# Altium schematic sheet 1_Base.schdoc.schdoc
size 309 x 223 mm; Symbol: Sheet-Symbol_A4; Device: Sheet-Symbol_A4; Company: Velizy Astro Club; Drawed: Paul V.; Reviewed: Denis G.; Version: V1.0; Page Size: A4; @Project Name: NAFA AstrAlim; @Page Count: 2; @Update Date: 2024-01-05; @Create Date: 2023-12-12; @Schematic Name: AstrAlim NAFA; Part Number: AstrAlim-v1.0; @Page No: 1; @Page Name: Base
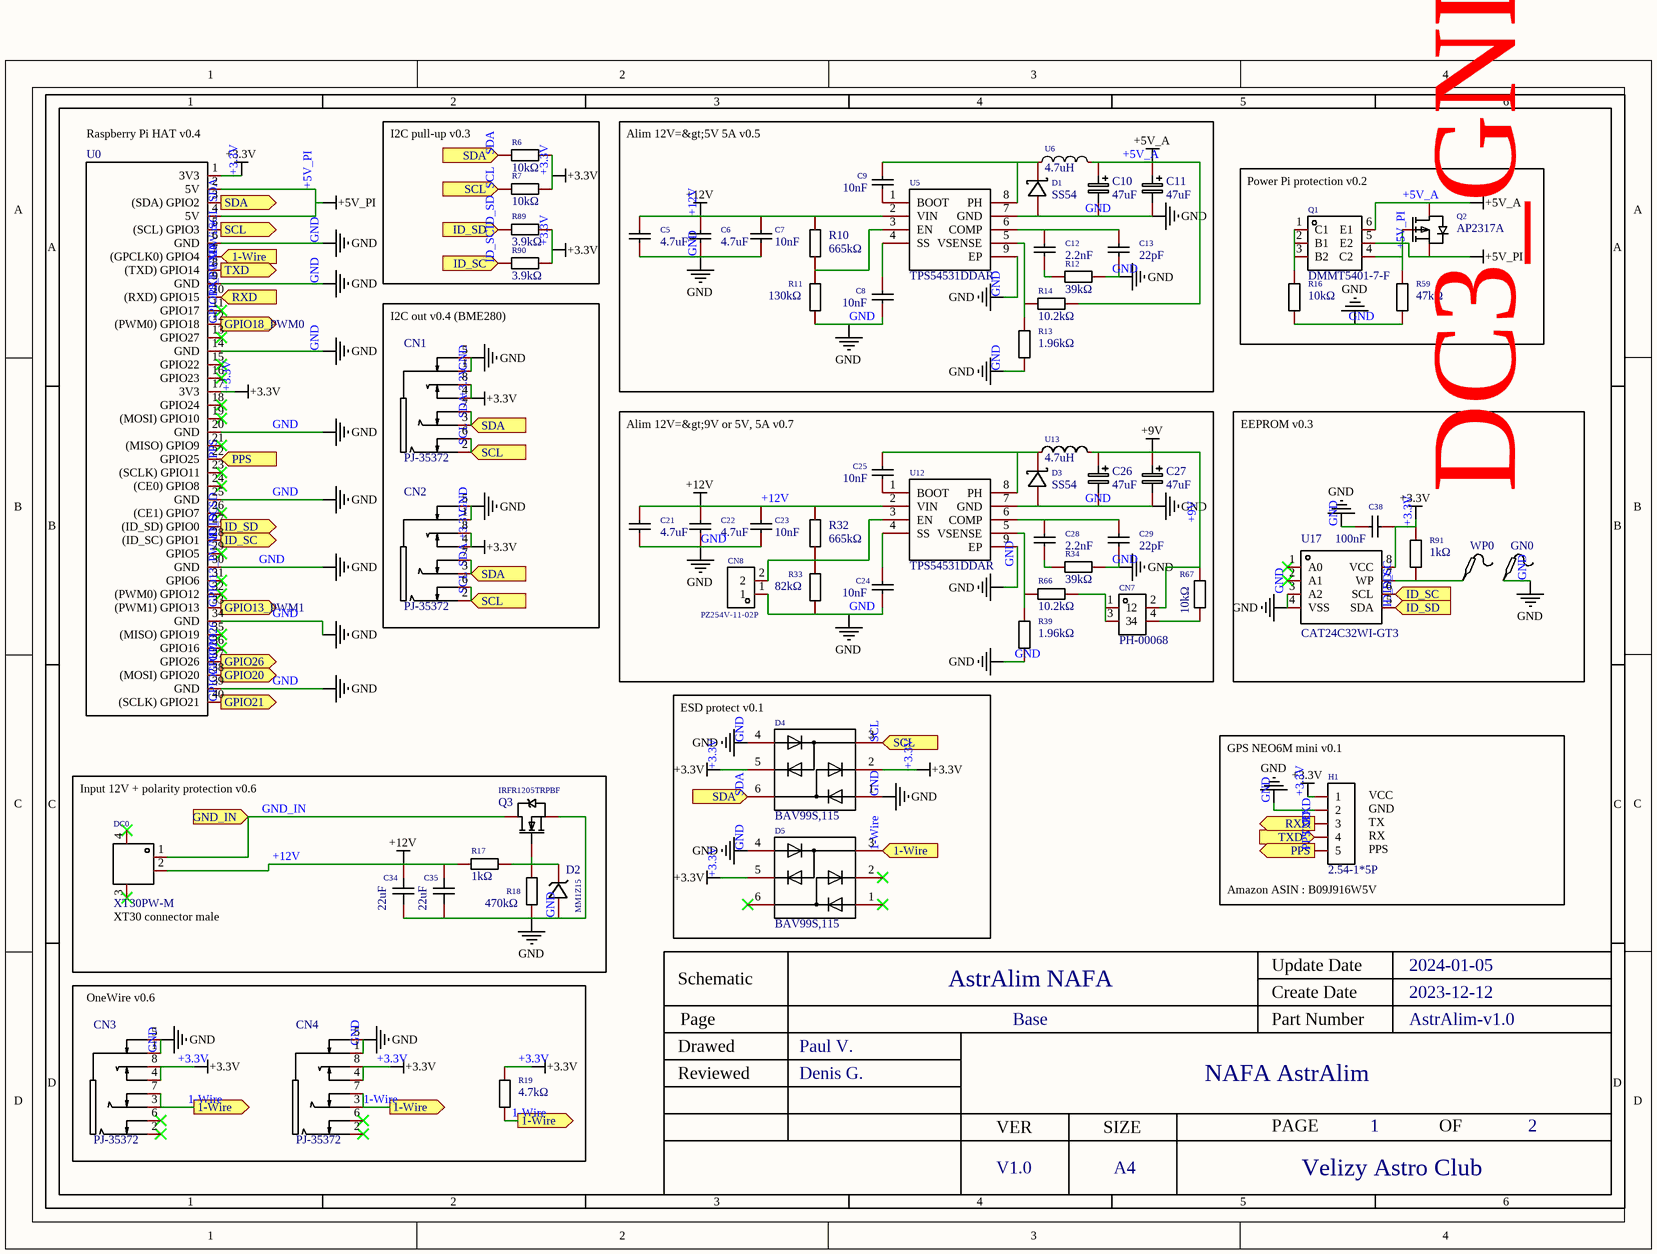
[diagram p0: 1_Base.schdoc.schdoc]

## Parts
C5  4.7uF  [C0805]
C6  4.7uF  [C0805]
C7  10nF  [C0402]
C8  10nF  [C0402]
C9  10nF  [C0402]
C10  47uF  [CAP-SMD_L3.5-W2.8-R-RD]
C11  47uF  [CAP-SMD_L3.5-W2.8-R-RD]
C12  2.2nF  [C0603]
C13  22pF  [C0402]
C21  4.7uF  [C0805]
C22  4.7uF  [C0805]
C23  10nF  [C0402]
C24  10nF  [C0402]
C25  10nF  [C0402]
C26  47uF  [CAP-SMD_L3.5-W2.8-R-RD]
C27  47uF  [CAP-SMD_L3.5-W2.8-R-RD]
C28  2.2nF  [C0603]
C29  22pF  [C0402]
C34  22uF  [C0805]
C35  22uF  [C0805]
C38  100nF  [C0402]
CN1  PJ-35372  [AUDIO-TH_PJ-35372]
CN2  PJ-35372  [AUDIO-TH_PJ-35372]
CN3  PJ-35372  [AUDIO-TH_PJ-35372]
CN4  PJ-35372  [AUDIO-TH_PJ-35372]
CN7  PH-00068  [HDR-TH_4P-P2.54-V-M-R2-C2-S2.54]
CN8  PZ254V-11-02P  [HDR-TH_2P-P2.54-V-M]
D1  SS54  [SMA_L4.4-W2.8-LS5.4-R-RD]
D2  MM1Z15  [SOD-123_L2.7-W1.6-LS3.7-RD]
D3  SS54  [SMA_L4.4-W2.8-LS5.4-R-RD]
D4  BAV99S,115  [SOT-363_L2.0-W1.3-P0.65-LS2.1-TL]
D5  BAV99S,115  [SOT-363_L2.0-W1.3-P0.65-LS2.1-TL]
DC0  XT30PW-M  [CONN-TH_XT30PW-F-1]
GN0  Test-Point  [Test-Point-0.5mm]  (value not drawn)
H1  2.54-1*5P  [HDR-TH_5P-P2.54-V-F]
Q1  DMMT5401-7-F  [SOT-23-6_L2.9-W1.6-P0.95-LS2.8-BR]
Q2  AP2317A  [SOT-23-3_L2.9-W1.6-P1.90-LS2.8-BR]
Q3  IRFR1205TRPBF  [TO-252-3_L6.5-W5.8-P4.58-BL]
R6  10kΩ  [R0402]
R7  10kΩ  [R0402]
R10  665kΩ  [R0603]
R11  130kΩ  [R0603]
R12  39kΩ  [R0603]
R13  1.96kΩ  [R0402]
R14  10.2kΩ  [R0402]
R16  10kΩ  [R0402]
R17  1kΩ  [R0402]
R18  470kΩ  [R0603]
R19  4.7kΩ  [R0402]
R32  665kΩ  [R0603]
R33  82kΩ  [R0603]
R34  39kΩ  [R0603]
R39  1.96kΩ  [R0402]
R59  47kΩ  [R0402]
R66  10.2kΩ  [R0402]
R67  10kΩ  [R0402]
R89  3.9kΩ  [R0603]
R90  3.9kΩ  [R0603]
R91  1kΩ  [R0402]
U0  RASPI HAT FULL  [RASBERRYPI-3-HAT-EXT]  (value not drawn)
U5  TPS54531DDAR  [SOIC-8_L5.0-W4.0-P1.27-LS6.0-BL-EP2.0]
U6  4.7uH  [IND-SMD_L7.2-W6.6_GPSR07X0]
U12  TPS54531DDAR  [SOIC-8_L5.0-W4.0-P1.27-LS6.0-BL-EP2.0]
U13  4.7uH  [IND-SMD_L7.2-W6.6_GPSR07X0]
U17  CAT24C32WI-GT3  [SOIC-8_L5.0-W4.0-P1.27-LS6.0-BL]
WP0  Test-Point  [Test-Point-0.5mm]  (value not drawn)

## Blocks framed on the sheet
I2C pull-up v0.3: R6 R7 R89 R90
Alim 12V=&gt;5V 5A v0.5: C5-C13 D1 R10-R14 U5 U6
Power Pi protection v0.2: Q1 Q2 R16 R59
I2C out v0.4 (BME280): CN1 CN2
Alim 12V=&gt;9V or 5V, 5A v0.7: C21-C29 CN7 CN8 D3 R32-R34 R39 R66 R67 U12 U13
EEPROM v0.3: C38 GN0 R91 U17 WP0
ESD protect v0.1: D4 D5
OneWire v0.6: CN3 CN4 R19

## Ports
1-Wire (in), 1-Wire (out), GND_IN (in), GPIO13_PWM1 (out), GPIO18_PWM0 (out), GPIO20 (out), GPIO21 (out), GPIO26 (out), ID_SC (in), ID_SC (out), ID_SD (in), ID_SD (out), PPS (in), PPS (out), RXD (in), RXD (out), SCL (in), SCL (out), SDA (in), SDA (out), TXD (in), TXD (out)

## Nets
+3.3V: C38.2 CN1.4 CN1.8 CN2.4 CN2.8 CN3.4 CN3.8 CN4.4 CN4.8 D4.2(C) D4.5(C) D5.5(C) H1.1 R6.2 R7.2 R19.2 R89.2 R90.2 R91.2 U0.1(3V3) U0.17(3V3) U17.8(VCC)
+5V_A: C10.1 C11.1 Q1.6(E1) Q2.3(D) R14.2 U6.2
+5V_PI: Q1.5(E2) Q2.2(S) U0.2(5V) U0.4(5V)
+9V: C26.1 C27.1 CN7.2 R67.2 U13.2
+12V: C5.2 C6.2 C7.2 C21.2 C22.2 C23.2 C34.2 C35.2 DC0.2 R10.2 R17.1 R32.2 U5.2(VIN) U12.2(VIN)
GND: C5.1 C6.1 C7.1 C8.1 C10.2 C11.2 C13.1 C21.1 C22.1 C23.1 C24.1 C26.2 C27.2 C29.1 C34.1 C35.1 C38.1 CN1.1 CN1.5 CN2.1 CN2.5 CN3.1 CN3.5 CN4.1 CN4.5 CN8.1 D1.1(A) D2.2(A) D3.1(A) D4.1(A) D4.4(A) D5.4(A) GN0.1 H1.2 Q3.3(S) R11.1 R12.2 R13.1 R16.1 R18.1 R33.1 R34.2 R39.1 R59.1 U0.6(GND) U0.9(GND) U0.14(GND) U0.20(GND) U0.25(GND) U0.30(GND) U0.34(GND) U0.39(GND) U5.7(GND) U5.9(EP) U12.7(GND) U12.9(EP) U17.3(A2) U17.4(VSS)
1-Wire: CN3.3 CN3.7 CN4.3 CN4.7 D5.3(AC) R19.1 U0.7((GPCLK0)_GPIO4) ; port 1-Wire
GND_IN: DC0.1 Q3.2(D) ; port GND_IN
GPIO13_PWM1: U0.33((PWM1)_GPIO13) ; port GPIO13_PWM1
GPIO18_PWM0: U0.12((PWM0)_GPIO18) ; port GPIO18_PWM0
GPIO20: U0.38((MOSI)_GPIO20) ; port GPIO20
GPIO21: U0.40((SCLK)_GPIO21) ; port GPIO21
GPIO26: U0.37(GPIO26) ; port GPIO26
ID_SC: R90.1 U0.28((ID_SC)_GPIO1) U17.6(SCL) ; port ID_SC
ID_SD: R89.1 U0.27((ID_SD)_GPIO0) U17.5(SDA) ; port ID_SD
PPS: H1.5 U0.22(GPIO25) ; port PPS
RXD: H1.3 U0.10((RXD)_GPIO15) ; port RXD
SCL: CN1.2 CN1.6 CN2.2 CN2.6 D4.3(AC) R7.1 U0.5((SCL)_GPIO3) ; port SCL
SDA: CN1.3 CN1.7 CN2.3 CN2.7 D4.6(AC) R6.1 U0.3((SDA)_GPIO2) ; port SDA
TXD: H1.4 U0.8((TXD)_GPIO14) ; port TXD
NetC8_2: C8.2 U5.4(SS)
NetC9_1: C9.1 U5.1(BOOT)
NetC9_2: C9.2 D1.2(K) U5.8(PH) U6.1
NetC12_1: C12.1 R12.1
NetC12_2: C12.2 C13.2 U5.6(COMP)
NetC24_2: C24.2 U12.4(SS)
NetC25_1: C25.1 U12.1(BOOT)
NetC25_2: C25.2 D3.2(K) U12.8(PH) U13.1
NetC28_1: C28.1 R34.1
NetC28_2: C28.2 C29.2 U12.6(COMP)
NetCN7_1: CN7.1 CN7.3 R66.2
NetCN7_4: CN7.4 R67.1
NetCN8_2: CN8.2 R32.1 R33.2 U12.3(EN)
NetD2_1: D2.1(C) Q3.1(G) R17.2 R18.2
NetQ1_1: Q1.1(C1) Q1.2(B1) Q1.3(B2) R16.2
NetQ1_4: Q1.4(C2) Q2.1(G) R59.2
NetR10_1: R10.1 R11.2 U5.3(EN)
NetR13_2: R13.2 R14.1 U5.5(VSENSE)
NetR39_2: R39.2 R66.1 U12.5(VSENSE)
NetR91_1: R91.1 U17.7(WP) WP0.1

Not connected (* = marked no-connect by the designer): CN3 2* 6*; CN4 2* 6*; D5 1(A)* 2(C)* 6(AC)*; DC0 3* 4*; U0 11(GPIO17)* 13(GPIO27)* 15(GPIO22)* 16(GPIO23)* 18(GPIO24)* 19((MOSI)_GPIO10)* 21((MISO)_GPIO9)* 23((SCLK)_GPIO11)* 24((CE0)_GPIO8)* 26((CE1)_GPIO7)* 29(GPIO5)* 31(GPIO6)* 32((PWM0)_GPIO12)* 35((MISO)_GPIO19)* 36(GPIO16)*; U17 1(A0)* 2(A1)*

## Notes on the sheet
- (near U0) Raspberry Pi HAT v0.4
- (near DC0) Input 12V + polarity protection v0.6
- (near H1) GPS NEO6M mini v0.1
- (near H1) VCC
- (near H1) PPS
- (near H1) RX
- (near H1) TX
- (near H1) GND
- (near DC0) XT30 connector male
- (near H1) Amazon ASIN :	B09J916W5V
- Labels drawn without touching a wire or pin: DC3_GND

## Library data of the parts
C5 C6 C21 C22 = CL21A475KAQNNNE: Capacitance: Tolerance:±10% Tolerance:±10% Voltage Rated: Temperature Coefficient:; Manufacturer: SAMSUNG(三星); Add into BOM: yes; Tolerance: ±10%
C7-C9 C23-C25 = CL05B103KB5NNNC: Capacitance: Tolerance:±10% Tolerance:±10% Voltage Rated: Temperature Coefficient:; Manufacturer: SAMSUNG(三星); Add into BOM: yes; Tolerance: ±10%
C10 C11 C26 C27 = CA45-B-16V-47uF-K: Capacitance: Tolerance:±10% Tolerance:±10% Rated Voltage: Equivalent Series Resistance(ESR):3Ω@100kHz Operating Temperature:-55℃~+125℃ Operating Temperature:-55℃~+125℃; Manufacturer: CEC(振华新云); Add into BOM: yes; Tolerance: ±10%
C12 C28 = 0603B222K500NT: Capacitance: Tolerance:±10% Tolerance:±10% Voltage Rated: Temperature Coefficient:; Manufacturer: FH(风华); Add into BOM: yes; Tolerance: ±10%
C13 C29 = 0402CG220J500NT: Capacitance: Tolerance:±5% Tolerance:±5% Voltage Rated: Temperature Coefficient:; Manufacturer: FH(风华); Add into BOM: yes; Tolerance: ±5%
C34 C35 = CL21A226MAQNNNE_C45783: Capacitance: Tolerance:±20% Tolerance:±20% Voltage Rated: Temperature Coefficient:; Manufacturer: SAMSUNG(三星); Add into BOM: yes; Tolerance: ±20%
C38 = CL05B104KO5NNNC: Capacitance: Tolerance:±10% Tolerance:±10% Voltage Rated: Temperature Coefficient:; Manufacturer: SAMSUNG(三星); Add into BOM: yes; Tolerance: ±10%
CN1-CN4 = PJ-35372: Connector Type:3.5mm耳机座 Current Rating (Max):0.5A Voltage Rating (Max):30V Operating Temperature Range:-20℃~+70℃ Operating Temperature Range:-20℃~+70℃ Welding Temperature (Max):235℃; Manufacturer: XKB Connectivity(中国星坤); Add into BOM: yes; Current Rating (Max): 0.5A; Voltage Rating (Max): 30V; Welding Temperature (Max): 235℃
CN7 = PH-00068: Pin Structure:2x2P Pitch:2.54mm Number of Pins:4P Mounting Type:Straight Number of Rows:双排 Row Spacing:2.54mm Circluar Pins/Square Pins:Square Pins Current Rating (Max):3A Voltage Rating (Max):- Length of Mating Pin:6mm Insulation Height:2.5mm Length of E; Manufacturer: Liansheng(连盛); Add into BOM: yes; Pin Structure: 2x2P; Pitch: 2.54mm; Current Rating (Max): 3A
CN8 = PZ254V-11-02P: Number of Rows:Plugin Number of Pins:2P Pitch:2.54mm Pin Structure:1x2P Row Spacing:- Mounting Type:Straight Circluar Pins/Square Pins:Square Pins Current Rating (Max):- Voltage Rating (Max):- Length of Mating Pin:6mm Insulation Height:2.5mm Length of End; Manufacturer: XFCN(兴飞); Add into BOM: yes; Pitch: 2.54mm; Pin Structure: 1x2P
D1 D3 = SS54_C22452: Forward Voltage (Vf@If):550mV@5A Reverse Voltage (Vr):40V Average Rectified Current (Io):5A Reverse Leakage Current (Ir):1mA@40V; Manufacturer: MDD; Add into BOM: yes; Reverse Voltage (Vr): 40V; Average Rectified Current (Io): 5A
D2 = MM1Z15_C86235: Diode Configuration:Single Zener Voltage (Nom):15V Zener Voltage (Range):13.8V~15.6V Zener Voltage (Range):13.8V~15.6V Tolerance:±5% Tolerance:±5% Power Dissipation:500mW Reverse Leakage Current (Ir):100nA@11V Zener Impedance (Zzt):40Ω; Manufacturer: ST(先科); Add into BOM: yes; Diode Configuration: Single; Zener Voltage (Nom): 15V; Tolerance: ±5%; Power Dissipation: 500mW; Zener Impedance (Zzt): 40Ω
D4 D5 = BAV99S,115: Diode Configuration:2 Pair Series Connection Forward Voltage (Vf@If):1.25V@150mA Reverse Voltage (Vr): Average Rectified Current (Io): Power Dissipation: Reverse Leakage Current:500nA@80V Reverse Recovery Time (trr): Operating Temperature:- Operating Temp; Manufacturer: Nexperia(安世); Symbol: BAV99S,135; Add into BOM: yes
DC0 = XT30PW-F: Brand:艾迈斯 Model:XT30PW-F Power:- Output:- Input:- Size:- Interface:- Type:- Colour:- MaximumCurrent:- Type:航模插头 RatedVoltage:- Type1:- NumberOfUSBHoles:- InterfaceType:母头 MetalMaterial:- InsulationMaterial:- RatedCurrent:- RecommendedWireGauge:- FlameReta; Manufacturer: AMASS(艾迈斯); Add into BOM: yes; Brand: 艾迈斯; InterfaceType: 母头
GN0 WP0 = Test-Point: Test Point 测试点; Add into BOM: yes
H1 = 2.54-1*5P母: Number of Rows:Plugin Number of Holes:5P Pitch:2.54mm Holes Structure:1x5P Row Spacing:- Mounting Type:Straight Insulation Height:- Contact Material:- Contact Plating:-; Manufacturer: BOOMELE(博穆精密); Symbol: Header-Female-2.54_1x5; Add into BOM: yes; Number of Holes: 5P; Pitch: 2.54mm; Holes Structure: 1x5P
Q1 = DMMT5401-7-F: Transistor Type: Collector Current (Ic): Collector-Emitter Breakdown Voltage (Vceo): Power Dissipation (Pd): DC Current Gain (hFE@Ic,Vce):60@10mA,5V DC Current Gain (hFE@Ic,Vce):60@10mA,5V Transition Frequency (fT):100MHz Collector Cut-Off Current (Icbo):; Manufacturer: DIODES(美台); Add into BOM: yes; Transition Frequency (fT): 100MHz; Collector Cut-Off Current (Icbo): 50nA; Collector-Emitter Saturation Voltage (VCE(sat)@Ic,Ib): 500mV@50mA,5mA
Q2 = AP2317A: Type: Drain Source Voltage (Vdss): Continuous Drain Current (Id): Power Dissipation (Pd): Drain Source On Resistance (RDS(on)@Vgs,Id):17mΩ@4.5V,6A Gate Threshold Voltage (Vgs(th)@Id):550mV@250uA Total Gate Charge (Qg@Vgs):19.5nC@4.5V Input Capacitance (Ci; Manufacturer: ALLPOWER(铨力); Add into BOM: yes; Input Capacitance (Ciss@Vds): 1.73nF@6V; Reverse Transfer Capacitance (Crss@Vds): 210pF@6V
Q3 = IRFR1205TRPBF: Type: Drain Source Voltage (Vdss): Continuous Drain Current (Id): Power Dissipation (Pd): Drain Source On Resistance (RDS(on)@Vgs,Id):27mΩ@10V,26A Gate Threshold Voltage (Vgs(th)@Id):4V@250uA Total Gate Charge (Qg@Vgs):65nC@10V Input Capacitance (Ciss@Vds; Manufacturer: Infineon(英飞凌); Add into BOM: yes; Input Capacitance (Ciss@Vds): 1300pF@25V
R6 R7 R16 R67 = 0402WGF1002TCE: Resistance:10000Ω Tolerance:±1% Tolerance:±1% Power(Watts): Overload Voltage (Max): Temperature Coefficient:±100ppm/℃ Temperature Coefficient:±100ppm/℃ Type:Thick Film Resistors Operating Temperature Range:-55℃~+155℃ Operating Temperature Range:-55℃~+155℃; Manufacturer: UNI-ROYAL(厚声); Add into BOM: yes; Tolerance: ±1%
R10 R32 = AC0603FR-07665KL: Type:Thick Film Resistors Resistance: Tolerance:±1% Tolerance:±1% Power(Watts): Temperature Coefficient:±100ppm/℃ Temperature Coefficient:±100ppm/℃ Overload Voltage (Max): Operating Temperature Range:-55℃~+155℃ Operating Temperature Range:-55℃~+155℃; Manufacturer: YAGEO(国巨); Add into BOM: yes; Tolerance: ±1%
R11 = 0603WAF1303T5E: Resistance:130000Ω Tolerance:±1% Tolerance:±1% Power(Watts): Overload Voltage (Max): Temperature Coefficient:±100ppm/℃ Temperature Coefficient:±100ppm/℃ Type:Thick Film Resistors Operating Temperature Range:-55℃~+155℃ Operating Temperature Range:-55℃~+155; Manufacturer: UNI-ROYAL(厚声); Add into BOM: yes; Tolerance: ±1%
R12 R34 = 0603WAF3902T5E: Resistance:39000Ω Tolerance:±1% Tolerance:±1% Power(Watts): Overload Voltage (Max): Temperature Coefficient:±100ppm/℃ Temperature Coefficient:±100ppm/℃ Type:Thick Film Resistors Operating Temperature Range:-55℃~+155℃ Operating Temperature Range:-55℃~+155℃; Manufacturer: UNI-ROYAL(厚声); Add into BOM: yes; Tolerance: ±1%
R13 R39 = 0402WGF1961TCE: Resistance:1960Ω Tolerance:±1% Tolerance:±1% Power(Watts): Overload Voltage (Max): Temperature Coefficient:±100ppm/℃ Temperature Coefficient:±100ppm/℃ Type:Thick Film Resistors Operating Temperature Range:-55℃~+155℃ Operating Temperature Range:-55℃~+155℃; Manufacturer: UNI-ROYAL(厚声); Add into BOM: yes; Tolerance: ±1%
R14 R66 = 0402WGF1022TCE: Resistance:10200Ω Tolerance:±1% Tolerance:±1% Power(Watts): Overload Voltage (Max): Temperature Coefficient:±100ppm/℃ Temperature Coefficient:±100ppm/℃ Type:Thick Film Resistors Operating Temperature Range:-55℃~+155℃ Operating Temperature Range:-55℃~+155℃; Manufacturer: UNI-ROYAL(厚声); Add into BOM: yes; Tolerance: ±1%
R17 R91 = 0402WGF1001TCE: Resistance:1000Ω Tolerance:±1% Tolerance:±1% Power(Watts): Overload Voltage (Max): Temperature Coefficient:±100ppm/℃ Temperature Coefficient:±100ppm/℃ Type:Thick Film Resistors Operating Temperature Range:-55℃~+155℃ Operating Temperature Range:-55℃~+155℃; Manufacturer: UNI-ROYAL(厚声); Add into BOM: yes; Tolerance: ±1%
R18 = 0603WAF4703T5E: Resistance:470000Ω Tolerance:±1% Tolerance:±1% Power(Watts): Overload Voltage (Max): Temperature Coefficient:±100ppm/℃ Temperature Coefficient:±100ppm/℃ Type:Thick Film Resistors Operating Temperature Range:-55℃~+155℃ Operating Temperature Range:-55℃~+155; Manufacturer: UNI-ROYAL(厚声); Add into BOM: yes; Tolerance: ±1%
R19 = 0402WGF4701TCE: Resistance:4700Ω Tolerance:±1% Tolerance:±1% Power(Watts): Overload Voltage (Max): Temperature Coefficient:±100ppm/℃ Temperature Coefficient:±100ppm/℃ Type:Thick Film Resistors Operating Temperature Range:-55℃~+155℃ Operating Temperature Range:-55℃~+155℃; Manufacturer: UNI-ROYAL(厚声); Add into BOM: yes; Tolerance: ±1%
R33 = 0603WAF8202T5E: Resistance:82000Ω Tolerance:±1% Tolerance:±1% Power(Watts): Overload Voltage (Max): Temperature Coefficient:±100ppm/℃ Temperature Coefficient:±100ppm/℃ Type:Thick Film Resistors Operating Temperature Range:-55℃~+155℃ Operating Temperature Range:-55℃~+155℃; Manufacturer: UNI-ROYAL(厚声); Add into BOM: yes; Tolerance: ±1%
R59 = 0402WGF4702TCE: Resistance:47000Ω Tolerance:±1% Tolerance:±1% Power(Watts): Overload Voltage (Max): Temperature Coefficient:±100ppm/℃ Temperature Coefficient:±100ppm/℃ Type:Thick Film Resistors Operating Temperature Range:-55℃~+155℃ Operating Temperature Range:-55℃~+155℃; Manufacturer: UNI-ROYAL(厚声); Add into BOM: yes; Tolerance: ±1%
R89 R90 = 0603WAF3901T5E: Resistance:3900Ω Tolerance:±1% Tolerance:±1% Power(Watts): Overload Voltage (Max): Temperature Coefficient:±100ppm/℃ Temperature Coefficient:±100ppm/℃ Type:Thick Film Resistors Operating Temperature Range:-55℃~+155℃ Operating Temperature Range:-55℃~+155℃; Manufacturer: UNI-ROYAL(厚声); Add into BOM: yes; Tolerance: ±1%
U0 = RASPI HAT FULL - NO OUTLINE: Manufacturer Part: RaspberryPi 3; Convert to PCB: yes; Add into BOM: no
U5 U12 = TPS54531DDAR: Function:Step-down type Synchronous Rectification:NO Output Type:Adjustable Number of Outputs:1 Topology:Step-down Input Voltage:3.5V~28V Input Voltage:3.5V~28V Output Voltage:0.8V~26.04V Output Voltage:0.8V~26.04V Output Current (Max):5A Switching Freque; Manufacturer: TI(德州仪器); Add into BOM: yes; Synchronous Rectification: NO; Number of Outputs: 1; Output Current (Max): 5A; Switching Frequency: 570kHz
U6 U13 = CYA0630-4.7UH: Inductance: Tolerance:±20% Tolerance:±20% Rated Current: DC Resistance (DCR):34.5mΩ; Manufacturer: SHOU HAN(首韩); Add into BOM: yes; Tolerance: ±20%; DC Resistance (DCR): 34.5mΩ
U17 = CAT24C32WI-GT3: Manufacturer: onsemi(安森美); Add into BOM: yes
